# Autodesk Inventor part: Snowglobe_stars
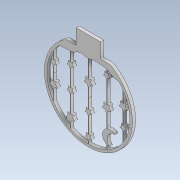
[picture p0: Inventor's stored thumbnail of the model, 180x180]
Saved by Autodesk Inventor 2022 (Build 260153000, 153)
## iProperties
Created: 2021-12
Part Number: Snowglobe_stars
Material: Generic
Document SubType Name: Modeling
Designer: allis
Density: 1 g/cm^3
Appearance: Default
Author: allis
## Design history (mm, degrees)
sketch "Sketch2"
  geometry: L1 (86.643, -29.961)-(86.636, -30.002); L2 (86.636, -30.002)-(86.622, -30.043); L3 (86.622, -30.043)-(86.622, -30.084); L4 (86.622, -30.084)-(86.621, -33.23); L5 (86.621, -33.23)-(86.621, -36.376); L6 (86.621, -36.376)-(86.62, -39.522); L7 (86.62, -39.522)-(86.62, -39.665); L8 (86.62, -39.665)-(86.645, -39.799); L9 (86.645, -39.799)-(86.712, -39.93); L10 (86.712, -39.93)-(87.046, -40.582); L11 (87.046, -40.582)-(87.381, -41.235); L12 (87.381, -41.235)-(87.703, -41.894); L13 (87.703, -41.894)-(87.812, -42.118); L14 (87.812, -42.118)-(87.961, -42.239); L15 (87.961, -42.239)-(88.213, -42.274); L16 (88.213, -42.274)-(88.897, -42.367); L17 (88.897, -42.367)-(89.579, -42.481); L18 (89.579, -42.481)-(90.262, -42.583); L19 (90.262, -42.583)-(90.467, -42.614); L20 (90.467, -42.614)-(90.652, -42.663); L21 (90.652, -42.663)-(90.723, -42.889); L22 (90.723, -42.889)-(90.791, -43.102); L23 (90.791, -43.102)-(90.662, -43.236); L24 (90.662, -43.236)-(90.53, -43.368); L25 (90.53, -43.368)-(90.05, -43.846); L26 (90.05, -43.846)-(89.578, -44.332); L27 (89.578, -44.332)-(89.087, -44.798); L28 (89.087, -44.798)-(88.855, -45.017); L29 (88.855, -45.017)-(88.796, -45.248); L30 (88.796, -45.248)-(88.857, -45.557); L31 (88.857, -45.557)-(88.984, -46.192); L32 (88.984, -46.192)-(89.079, -46.835); L33 (89.079, -46.835)-(89.192, -47.473); L34 (89.192, -47.473)-(89.229, -47.679); L35 (89.229, -47.679)-(89.235, -47.871); L36 (89.235, -47.871)-(89.041, -48.005); L37 (89.041, -48.005)-(88.858, -48.131); L38 (88.858, -48.131)-(88.69, -48.034); L39 (88.69, -48.034)-(88.526, -47.951); L40 (88.526, -47.951)-(88.047, -47.711); L41 (88.047, -47.711)-(87.569, -47.468); L42 (87.569, -47.468)-(87.09, -47.227); L43 (87.09, -47.227)-(86.626, -46.994); L44 (86.626, -46.994)-(86.62, -46.996); L45 (86.62, -46.996)-(86.62, -47.529); L46 (86.62, -47.529)-(86.619, -51.338); L47 (86.619, -51.338)-(86.648, -55.147); L48 (86.648, -55.147)-(86.601, -58.956); L49 (86.601, -58.956)-(86.588, -60.009); L50 (86.588, -60.009)-(86.749, -60.964); L51 (86.749, -60.964)-(87.317, -61.846); L52 (87.317, -61.846)-(87.325, -61.858); L53 (87.325, -61.858)-(87.332, -61.871); L54 (87.332, -61.871)-(87.337, -61.884); L55 (87.337, -61.884)-(87.44, -62.175); L56 (87.44, -62.175)-(87.662, -62.278); L57 (87.662, -62.278)-(87.955, -62.311); L58 (87.955, -62.311)-(88.417, -62.363); L59 (88.417, -62.363)-(88.878, -62.427); L60 (88.878, -62.427)-(89.335, -62.513); L61 (89.335, -62.513)-(89.779, -62.597); L62 (89.779, -62.597)-(89.85, -62.827); L63 (89.85, -62.827)-(89.541, -63.149); L64 (89.541, -63.149)-(89.19, -63.516)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; 1 further point
  constraints: 7 other
extrude "Extrusion2" new body sketch "Sketch2" distance "d2" = 3.175; taper "d3" = 0 deg
feature "Move Body1"
body "Solid2"
other parameters: "d4" = 90 deg
